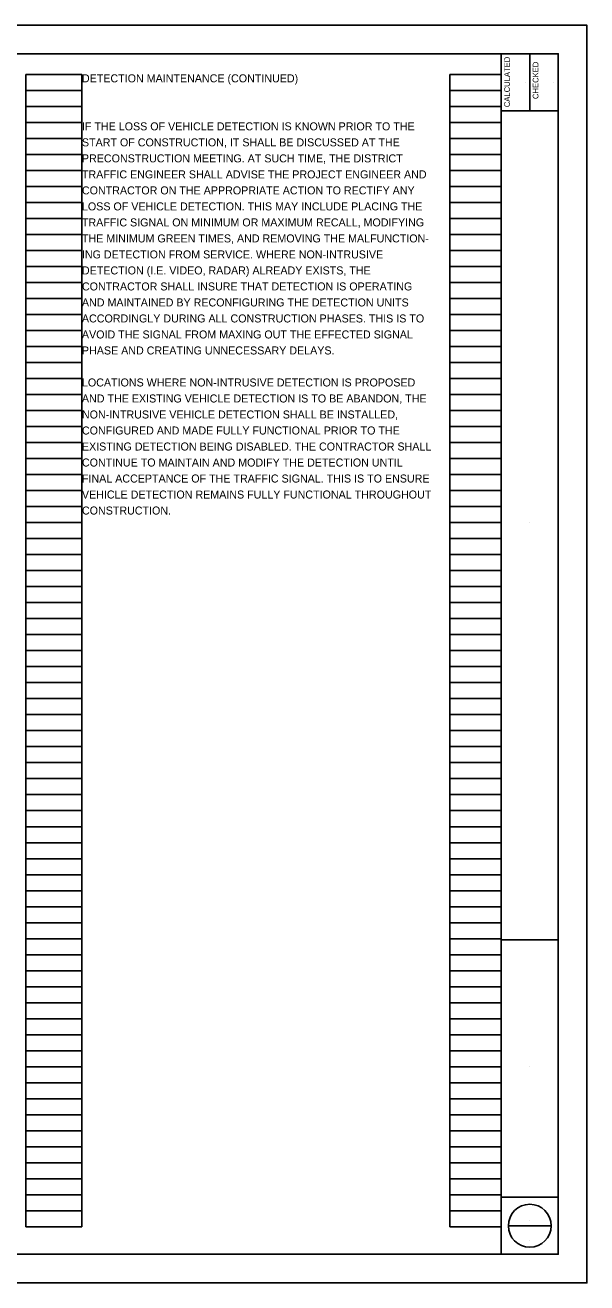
# Model space of a CAD drawing. Extents: x -11.8 to 65.2, y -26.4 to 34.6.
# Drawn here: x 24.17 to 34, y 0 to 22 of the extents above; entities that cross this region are included whole.
import ezdxf

# ---------------------------------------------------------------- set-up
doc = ezdxf.new("R2010")
doc.units = 0
for name, color, linetype in [('SH_Border', 7, 'Continuous'), ('SH_Cut_Line', 7, 'Continuous'), ('SH_Data', 7, 'Continuous'), ('SH_Text', 7, 'Continuous')]:
    doc.layers.add(name, color=color, linetype=linetype)

msp = doc.modelspace()

# ---------------------------------------------------------------- linework, layer by layer
at = {"layer": 'SH_Border'}
for p, q in [((32.501, 0.5), (32.501, 21.5)), ((33.001, 21.5), (33.001, 20.5)), ((32.501, 20.5), (33.501, 20.5)), ((32.501, 6), (33.501, 6)), ((32.501, 1.5), (33.501, 1.5))]:
    msp.add_line(p, q, dxfattribs=at)
msp.add_lwpolyline([(2.001, 21.5), (33.501, 21.5), (33.501, 0.5), (2.001, 0.5)], close=True, dxfattribs=at)
at = {"layer": 'SH_Cut_Line'}
msp.add_lwpolyline([(0.001, 0), (34.001, 0), (34.001, 22), (0.001, 22)], close=True, dxfattribs=at)
at = {"layer": 'SH_Data'}
for p, q in [((24.181, 0.98), (24.181, 21.14)), ((24.181, 21.14), (25.161, 21.14)), ((25.161, 0.98), (25.161, 21.14)), ((31.601, 0.98), (31.601, 21.14)), ((31.601, 21.14), (32.501, 21.14)), ((32.501, 0.98), (32.501, 21.14)), ((32.921, 21.004), (32.921, 21.004)), ((33.421, 21.004), (33.421, 21.004)), ((24.181, 20.86), (25.161, 20.86)), ((31.601, 20.86), (32.501, 20.86)), ((24.181, 20.58), (25.161, 20.58)), ((31.601, 20.58), (32.501, 20.58)), ((24.181, 20.3), (25.161, 20.3)), ((31.601, 20.3), (32.501, 20.3)), ((24.181, 20.02), (25.161, 20.02)), ((31.601, 20.02), (32.501, 20.02)), ((24.181, 19.74), (25.161, 19.74)), ((31.601, 19.74), (32.501, 19.74)), ((24.181, 19.46), (25.161, 19.46)), ((31.601, 19.46), (32.501, 19.46)), ((24.181, 19.18), (25.161, 19.18)), ((31.601, 19.18), (32.501, 19.18)), ((24.181, 18.9), (25.161, 18.9)), ((31.601, 18.9), (32.501, 18.9)), ((24.181, 18.62), (25.161, 18.62)), ((31.601, 18.62), (32.501, 18.62)), ((24.181, 18.34), (25.161, 18.34)), ((31.601, 18.34), (32.501, 18.34)), ((24.181, 18.06), (25.161, 18.06)), ((31.601, 18.06), (32.501, 18.06)), ((24.181, 17.78), (25.161, 17.78)), ((31.601, 17.78), (32.501, 17.78)), ((24.181, 17.5), (25.161, 17.5)), ((31.601, 17.5), (32.501, 17.5)), ((24.181, 17.22), (25.161, 17.22)), ((31.601, 17.22), (32.501, 17.22)), ((24.181, 16.94), (25.161, 16.94)), ((31.601, 16.94), (32.501, 16.94)), ((24.181, 16.66), (25.161, 16.66)), ((31.601, 16.66), (32.501, 16.66)), ((24.181, 16.38), (25.161, 16.38)), ((31.601, 16.38), (32.501, 16.38)), ((24.181, 16.1), (25.161, 16.1)), ((31.601, 16.1), (32.501, 16.1)), ((24.181, 15.82), (25.161, 15.82)), ((31.601, 15.82), (32.501, 15.82)), ((24.181, 15.54), (25.161, 15.54)), ((31.601, 15.54), (32.501, 15.54)), ((24.181, 15.26), (25.161, 15.26)), ((31.601, 15.26), (32.501, 15.26)), ((24.181, 14.98), (25.161, 14.98)), ((31.601, 14.98), (32.501, 14.98)), ((24.181, 14.7), (25.161, 14.7)), ((31.601, 14.7), (32.501, 14.7)), ((24.181, 14.42), (25.161, 14.42)), ((31.601, 14.42), (32.501, 14.42)), ((24.181, 14.14), (25.161, 14.14)), ((31.601, 14.14), (32.501, 14.14)), ((24.181, 13.86), (25.161, 13.86)), ((31.601, 13.86), (32.501, 13.86)), ((24.181, 13.58), (25.161, 13.58)), ((31.601, 13.58), (32.501, 13.58)), ((24.181, 13.3), (25.161, 13.3)), ((31.601, 13.3), (32.501, 13.3)), ((33.001, 13.292), (33.001, 13.292)), ((24.181, 13.02), (25.161, 13.02)), ((31.601, 13.02), (32.501, 13.02)), ((24.181, 12.74), (25.161, 12.74)), ((31.601, 12.74), (32.501, 12.74)), ((24.181, 12.46), (25.161, 12.46)), ((31.601, 12.46), (32.501, 12.46)), ((24.181, 12.18), (25.161, 12.18)), ((31.601, 12.18), (32.501, 12.18)), ((24.181, 11.9), (25.161, 11.9)), ((31.601, 11.9), (32.501, 11.9)), ((24.181, 11.62), (25.161, 11.62)), ((31.601, 11.62), (32.501, 11.62)), ((24.181, 11.34), (25.161, 11.34)), ((31.601, 11.34), (32.501, 11.34)), ((24.181, 11.06), (25.161, 11.06)), ((31.601, 11.06), (32.501, 11.06)), ((24.181, 10.78), (25.161, 10.78)), ((31.601, 10.78), (32.501, 10.78)), ((24.181, 10.5), (25.161, 10.5)), ((31.601, 10.5), (32.501, 10.5)), ((24.181, 10.22), (25.161, 10.22)), ((31.601, 10.22), (32.501, 10.22)), ((24.181, 9.94), (25.161, 9.94)), ((31.601, 9.94), (32.501, 9.94)), ((24.181, 9.66), (25.161, 9.66)), ((31.601, 9.66), (32.501, 9.66)), ((24.181, 9.38), (25.161, 9.38)), ((31.601, 9.38), (32.501, 9.38)), ((24.181, 9.1), (25.161, 9.1)), ((31.601, 9.1), (32.501, 9.1)), ((24.181, 8.82), (25.161, 8.82)), ((31.601, 8.82), (32.501, 8.82)), ((24.181, 8.54), (25.161, 8.54)), ((31.601, 8.54), (32.501, 8.54)), ((24.181, 8.26), (25.161, 8.26)), ((31.601, 8.26), (32.501, 8.26)), ((24.181, 7.98), (25.161, 7.98)), ((31.601, 7.98), (32.501, 7.98)), ((24.181, 7.7), (25.161, 7.7)), ((31.601, 7.7), (32.501, 7.7)), ((24.181, 7.42), (25.161, 7.42)), ((31.601, 7.42), (32.501, 7.42)), ((24.181, 7.14), (25.161, 7.14)), ((31.601, 7.14), (32.501, 7.14)), ((24.181, 6.86), (25.161, 6.86)), ((31.601, 6.86), (32.501, 6.86)), ((24.181, 6.58), (25.161, 6.58)), ((31.601, 6.58), (32.501, 6.58)), ((24.181, 6.3), (25.161, 6.3)), ((31.601, 6.3), (32.501, 6.3)), ((24.181, 6.02), (25.161, 6.02)), ((31.601, 6.02), (32.501, 6.02)), ((24.181, 5.74), (25.161, 5.74)), ((31.601, 5.74), (32.501, 5.74)), ((24.181, 5.46), (25.161, 5.46)), ((31.601, 5.46), (32.501, 5.46)), ((24.181, 5.18), (25.161, 5.18)), ((31.601, 5.18), (32.501, 5.18)), ((24.181, 4.9), (25.161, 4.9)), ((31.601, 4.9), (32.501, 4.9)), ((24.181, 4.62), (25.161, 4.62)), ((31.601, 4.62), (32.501, 4.62)), ((24.181, 4.34), (25.161, 4.34)), ((31.601, 4.34), (32.501, 4.34)), ((24.181, 4.06), (25.161, 4.06)), ((31.601, 4.06), (32.501, 4.06)), ((24.181, 3.78), (25.161, 3.78)), ((31.601, 3.78), (32.501, 3.78)), ((33.001, 3.792), (33.001, 3.792)), ((24.181, 3.5), (25.161, 3.5)), ((31.601, 3.5), (32.501, 3.5)), ((24.181, 3.22), (25.161, 3.22)), ((31.601, 3.22), (32.501, 3.22)), ((24.181, 2.94), (25.161, 2.94)), ((31.601, 2.94), (32.501, 2.94)), ((24.181, 2.66), (25.161, 2.66)), ((31.601, 2.66), (32.501, 2.66)), ((24.181, 2.38), (25.161, 2.38)), ((31.601, 2.38), (32.501, 2.38)), ((24.181, 2.1), (25.161, 2.1)), ((31.601, 2.1), (32.501, 2.1)), ((24.181, 1.82), (25.161, 1.82)), ((31.601, 1.82), (32.501, 1.82)), ((24.181, 1.54), (25.161, 1.54)), ((31.601, 1.54), (32.501, 1.54)), ((24.181, 1.26), (25.161, 1.26)), ((31.601, 1.26), (32.501, 1.26)), ((24.181, 0.98), (25.161, 0.98)), ((31.601, 0.98), (32.501, 0.98)), ((32.626, 1), (33.376, 1)), ((33.001, 1.085), (33.001, 1.085)), ((33.001, 0.745), (33.001, 0.745))]:
    msp.add_line(p, q, dxfattribs=at)
msp.add_circle((33.001, 1), 0.375, dxfattribs=at)

# ---------------------------------------------------------------- texts
for s, p in [('CALCULATED', (32.653, 20.565)), ('CHECKED', (33.153, 20.708))]:
    msp.add_text(s, height=0.1, rotation=90, dxfattribs=at).set_placement(p)
at = {"layer": 'SH_Text'}
for s, p in [('DETECTION MAINTENANCE (CONTINUED)', (25.161, 21)), ('IF THE LOSS OF VEHICLE DETECTION IS KNOWN PRIOR TO THE', (25.161, 20.16)), ('START OF CONSTRUCTION, IT SHALL BE DISCUSSED AT THE', (25.161, 19.88)), ('PRECONSTRUCTION MEETING. AT SUCH TIME, THE DISTRICT', (25.161, 19.6)), ('TRAFFIC ENGINEER SHALL ADVISE THE PROJECT ENGINEER AND', (25.161, 19.32)), ('CONTRACTOR ON THE APPROPRIATE ACTION TO RECTIFY ANY', (25.161, 19.04)), ('LOSS OF VEHICLE DETECTION. THIS MAY INCLUDE PLACING THE', (25.161, 18.76)), ('TRAFFIC SIGNAL ON MINIMUM OR MAXIMUM RECALL, MODIFYING', (25.161, 18.48)), ('THE MINIMUM GREEN TIMES, AND REMOVING THE MALFUNCTION-', (25.161, 18.2)), ('ING DETECTION FROM SERVICE. WHERE NON-INTRUSIVE', (25.161, 17.92)), ('DETECTION (I.E. VIDEO, RADAR) ALREADY EXISTS, THE', (25.161, 17.64)), ('CONTRACTOR SHALL INSURE THAT DETECTION IS OPERATING', (25.161, 17.36)), ('AND MAINTAINED BY RECONFIGURING THE DETECTION UNITS', (25.161, 17.08)), ('ACCORDINGLY DURING ALL CONSTRUCTION PHASES. THIS IS TO', (25.161, 16.8)), ('AVOID THE SIGNAL FROM MAXING OUT THE EFFECTED SIGNAL', (25.161, 16.52)), ('PHASE AND CREATING UNNECESSARY DELAYS.', (25.161, 16.24)), ('LOCATIONS WHERE NON-INTRUSIVE DETECTION IS PROPOSED', (25.161, 15.68)), ('AND THE EXISTING VEHICLE DETECTION IS TO BE ABANDON, THE', (25.161, 15.4)), ('NON-INTRUSIVE VEHICLE DETECTION SHALL BE INSTALLED,', (25.161, 15.12)), ('CONFIGURED AND MADE FULLY FUNCTIONAL PRIOR TO THE', (25.161, 14.84)), ('EXISTING DETECTION BEING DISABLED. THE CONTRACTOR SHALL', (25.161, 14.56)), ('CONTINUE TO MAINTAIN AND MODIFY THE DETECTION UNTIL', (25.161, 14.28)), ('FINAL ACCEPTANCE OF THE TRAFFIC SIGNAL. THIS IS TO ENSURE', (25.161, 14)), ('VEHICLE DETECTION REMAINS FULLY FUNCTIONAL THROUGHOUT', (25.161, 13.72)), ('CONSTRUCTION.', (25.161, 13.44))]:
    msp.add_text(s, height=0.14, dxfattribs=at).set_placement(p)

doc.saveas('drawing.dxf')
